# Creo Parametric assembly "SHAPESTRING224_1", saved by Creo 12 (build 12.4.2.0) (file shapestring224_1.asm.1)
Units: Custom; MM, KILOGRAM, SECS

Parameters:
  PTC_WM_ITERATION = "0"
  PTC_WM_VERSION = "-.0"
  PTC_WM_LIFECYCLE_STATE = "In Work"
  PTC_WM_LIFECYCLE = "MO_CADDocument"
  PTC_WM_CREATED_BY = "Maximilian Roepper (Z0017RMS: MO)"
  PTC_WM_CREATED_ON = "18-Sep-26 11:36:42 AM"
  PTC_WM_MODIFIED_BY = "Maximilian Roepper (Z0017RMS: MO)"
  PTC_WM_MODIFIED_ON = "18-Sep-26 11:36:46 AM"
  PDMLINKNUMBER = "PDM000071454793"
  PTC_WM_NAME = "shapestring224_1.asm"
  PTC_WM_NUMBER = "PDM000071454793"

Other parameters: WEIGHT, WEIGHT_FACTOR, WEIGHT_ADD, MC_ERRORS, SUPPLIER, ISPOSITIONINGASSEMBLY

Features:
  1. coordinate system
  2. imported feature
  3. component "SHAPESTRING087_1"
  4. component "SHAPESTRING223_1"

Other named items: DRW_VIEW_ORG, ROUGH-GROB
